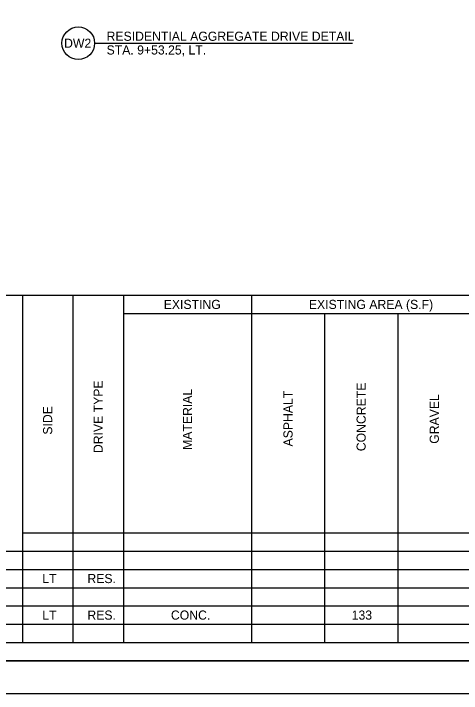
# Model space of a CAD drawing. Extents: x -1.2 to 34, y 0 to 22.
# Drawn here: x 13.8 to 20.66, y 0 to 10.42 of the extents above; entities that cross this region are included whole.
import ezdxf

# ---------------------------------------------------------------- set-up
doc = ezdxf.new("R2010")
doc.units = 0
for name, color, linetype in [('SH_Border', 7, 'Continuous'), ('SH_Cut_Line', 7, 'Continuous'), ('SH_Data', 7, 'Continuous'), ('SH_Text', 7, 'Continuous')]:
    doc.layers.add(name, color=color, linetype=linetype)

msp = doc.modelspace()

# ---------------------------------------------------------------- linework, layer by layer
at = {"layer": 'SH_Border'}
msp.add_lwpolyline([(1.5, 21.5), (33.5, 21.5), (33.5, 0.5), (1.5, 0.5)], close=True, dxfattribs=at)
at = {"layer": 'SH_Cut_Line'}
msp.add_lwpolyline([(0, 0), (34, 0), (34, 22), (0, 22)], close=True, dxfattribs=at)
at = {"layer": 'SH_Data'}
for p, q in [((10.456, 6.1), (32, 6.1)), ((13.932, 6.1), (13.932, 0.78)), ((14.706, 6.1), (14.706, 0.78)), ((15.48, 6.1), (15.48, 0.78)), ((17.44, 6.1), (17.44, 0.78)), ((15.48, 5.82), (32, 5.82)), ((18.56, 5.82), (18.56, 0.78)), ((19.68, 5.82), (19.68, 0.78)), ((13.932, 2.46), (32, 2.46)), ((10.456, 2.18), (32, 2.18)), ((10.456, 1.9), (32, 1.9)), ((10.456, 1.62), (32, 1.62)), ((10.456, 1.34), (32, 1.34)), ((10.456, 1.06), (32, 1.06)), ((10.456, 0.78), (32, 0.78)), ((10.456, 0.5), (32, 0.5))]:
    msp.add_line(p, q, dxfattribs=at)
at = {"layer": 'SH_Text'}
msp.add_line((15.039, 9.962), (18.988, 9.962), dxfattribs=at)
msp.add_circle((14.789, 9.962), 0.25, dxfattribs=at)

# ---------------------------------------------------------------- texts
for s, p in [('RESIDENTIAL AGGREGATE DRIVE DETAIL', (15.222, 9.999)), ('DW2', (14.571, 9.892)), ('STA. 9+53.25, LT.', (15.222, 9.789)), ('EXISTING', (16.097, 5.89)), ('EXISTING AREA (S.F)', (18.319, 5.89)), ('LT', (14.237, 1.69)), ('RES.', (14.928, 1.69)), ('LT', (14.237, 1.13)), ('RES.', (14.928, 1.13)), ('CONC.', (16.207, 1.13)), ('133', (18.975, 1.13))]:
    msp.add_text(s, height=0.14, dxfattribs=at).set_placement(p)
for s, p in [('DRIVE TYPE', (15.163, 3.682)), ('CONCRETE', (19.19, 3.711)), ('MATERIAL', (16.53, 3.731)), ('ASPHALT', (18.07, 3.784)), ('GRAVEL', (20.31, 3.825)), ('SIDE', (14.389, 3.965))]:
    msp.add_text(s, height=0.14, rotation=90, dxfattribs=at).set_placement(p)

doc.saveas('drawing.dxf')
